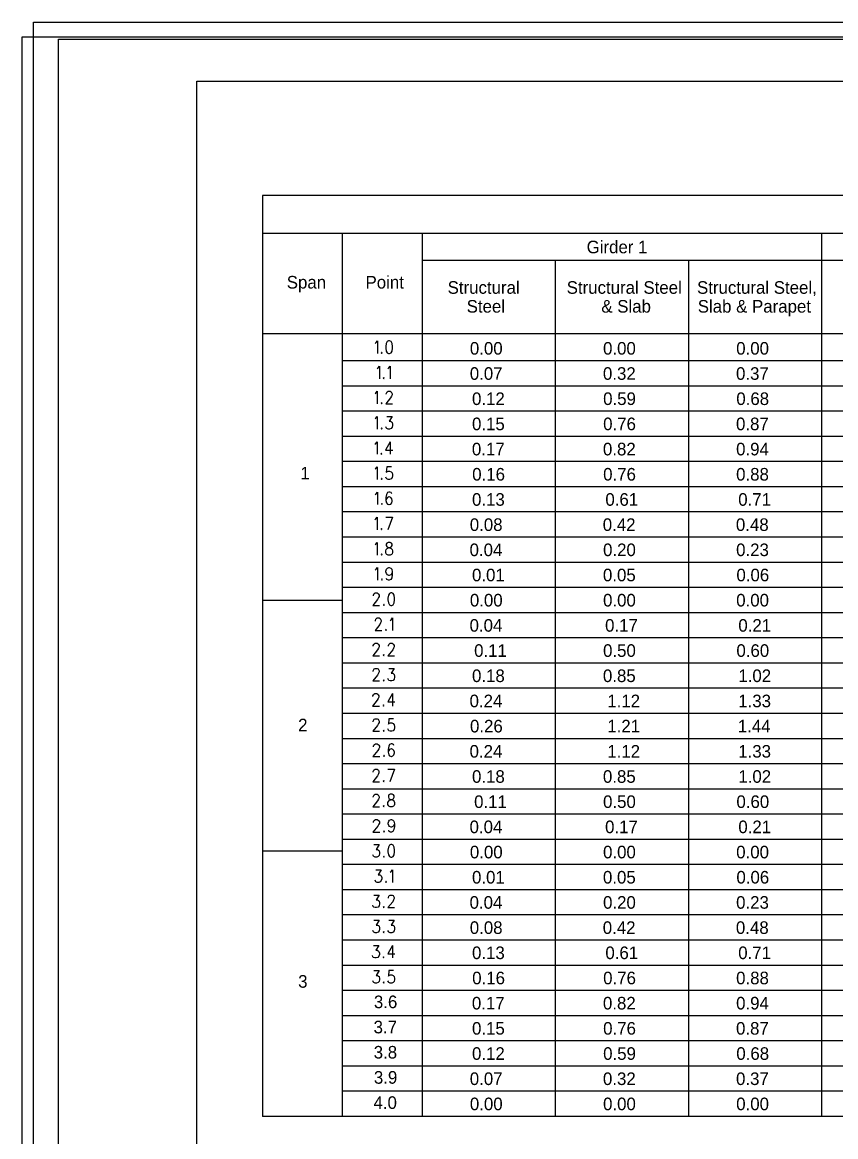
# Model space of a CAD drawing. Extents: x 208.5 to 250.5, y 328.7 to 350.7.
# Drawn here: x 208.55 to 216.62, y 339.65 to 350.71 of the extents above; entities that cross this region are included whole.
import ezdxf

# ---------------------------------------------------------------- set-up
doc = ezdxf.new("R2010")
doc.units = 0
for name, color, linetype in [('border', 7, 'Continuous'), ('Border 2660-Hwy18 - Level 62', 7, 'Continuous'), ('Border 2660-Hwy18 - Level 63', 7, 'Continuous'), ('Level 62 PDF', 7, 'Continuous'), ('Steel', 7, 'Continuous'), ('Text', 7, 'Continuous')]:
    doc.layers.add(name, color=color, linetype=linetype)

msp = doc.modelspace()

# ---------------------------------------------------------------- linework, layer by layer
at = {"layer": 'border'}
for p, q in [((210.28, 350.129), (242.291, 350.129)), ((210.28, 329.584), (210.28, 350.129))]:
    msp.add_line(p, q, dxfattribs=at)
at = {"layer": 'Border 2660-Hwy18 - Level 62'}
msp.add_lwpolyline([(208.659, 350.715), (242.778, 350.715), (242.778, 328.905), (208.659, 328.905)], close=True, dxfattribs=at)
at = {"layer": 'Border 2660-Hwy18 - Level 63'}
msp.add_lwpolyline([(208.548, 350.572), (242.548, 350.572), (242.548, 329.202), (208.548, 329.202)], close=True, dxfattribs=at)
at = {"layer": 'Level 62 PDF'}
msp.add_lwpolyline([(208.909, 350.548), (243.028, 350.548), (243.028, 328.739), (208.909, 328.739)], close=True, dxfattribs=at)
at = {"layer": 'Steel'}
for p, q in [((210.932, 348.995), (210.932, 339.854)), ((232.347, 348.995), (210.932, 348.995)), ((232.347, 348.618), (210.932, 348.618)), ((211.725, 348.618), (211.725, 339.854)), ((212.517, 348.618), (212.517, 339.854)), ((216.483, 348.618), (216.483, 339.854)), ((232.347, 348.349), (212.517, 348.349)), ((213.839, 348.349), (213.839, 339.854)), ((215.161, 348.349), (215.161, 339.854)), ((232.347, 347.623), (210.932, 347.623)), ((232.347, 347.354), (211.725, 347.354)), ((232.347, 347.104), (211.725, 347.104)), ((232.347, 346.854), (211.725, 346.854)), ((232.347, 346.604), (211.725, 346.604)), ((232.347, 346.354), (211.725, 346.354)), ((232.347, 346.104), (211.725, 346.104)), ((232.347, 345.854), (211.725, 345.854)), ((232.347, 345.604), (211.725, 345.604)), ((232.347, 345.354), (211.725, 345.354)), ((232.347, 345.104), (211.725, 345.104)), ((211.725, 344.976), (210.932, 344.976)), ((232.347, 344.854), (211.725, 344.854)), ((232.347, 344.604), (211.725, 344.604)), ((232.347, 344.354), (211.725, 344.354)), ((232.347, 344.104), (211.725, 344.104)), ((232.347, 343.854), (211.725, 343.854)), ((232.347, 343.604), (211.725, 343.604)), ((232.347, 343.354), (211.725, 343.354)), ((232.347, 343.104), (211.725, 343.104)), ((232.347, 342.854), (211.725, 342.854)), ((232.347, 342.604), (211.725, 342.604)), ((211.725, 342.486), (210.932, 342.486)), ((232.347, 342.354), (211.725, 342.354)), ((232.347, 342.104), (211.725, 342.104)), ((232.347, 341.854), (211.725, 341.854)), ((232.347, 341.604), (211.725, 341.604)), ((232.347, 341.354), (211.725, 341.354)), ((232.347, 341.104), (211.725, 341.104)), ((232.347, 340.854), (211.725, 340.854)), ((232.347, 340.604), (211.725, 340.604)), ((232.347, 340.354), (211.725, 340.354)), ((232.347, 340.104), (211.725, 340.104)), ((232.347, 339.854), (210.932, 339.854))]:
    msp.add_line(p, q, dxfattribs=at)
at = {"layer": 'Text'}
for p, q in [((212.202, 346.552), (212.202, 346.427)), ((212.157, 345.802), (212.224, 345.802)), ((212.224, 345.802), (212.176, 345.677)), ((212.223, 344.052), (212.223, 343.927)), ((212.178, 343.302), (212.245, 343.302)), ((212.245, 343.302), (212.197, 343.177)), ((212.223, 341.552), (212.223, 341.427))]:
    msp.add_line(p, q, dxfattribs=at)
for points in [[(212.051, 347.528), (212.06, 347.535), (212.074, 347.552), (212.074, 347.427)], [(212.185, 347.552), (212.171, 347.546), (212.161, 347.528), (212.157, 347.498), (212.157, 347.481), (212.161, 347.451), (212.171, 347.433), (212.185, 347.427), (212.195, 347.427), (212.209, 347.433), (212.219, 347.451), (212.224, 347.481), (212.224, 347.498), (212.219, 347.528), (212.209, 347.546), (212.195, 347.552), (212.185, 347.552)], [(212.116, 347.439), (212.111, 347.433), (212.116, 347.427), (212.121, 347.433), (212.116, 347.439)], [(212.071, 347.278), (212.081, 347.285), (212.095, 347.302), (212.095, 347.177)], [(212.178, 347.278), (212.188, 347.285), (212.202, 347.302), (212.202, 347.177)], [(212.137, 347.189), (212.132, 347.183), (212.137, 347.177), (212.141, 347.183), (212.137, 347.189)], [(212.05, 347.028), (212.059, 347.035), (212.073, 347.052), (212.073, 346.927)], [(212.161, 347.022), (212.161, 347.028), (212.166, 347.04), (212.171, 347.046), (212.18, 347.052), (212.199, 347.052), (212.209, 347.046), (212.213, 347.04), (212.219, 347.028), (212.219, 347.016), (212.213, 347.004), (212.204, 346.986), (212.157, 346.927), (212.224, 346.927)], [(212.115, 346.939), (212.11, 346.933), (212.115, 346.927), (212.12, 346.933), (212.115, 346.939)], [(212.05, 346.778), (212.059, 346.785), (212.073, 346.802), (212.073, 346.677)], [(212.166, 346.802), (212.219, 346.802), (212.19, 346.754), (212.204, 346.754), (212.213, 346.748), (212.219, 346.742), (212.224, 346.725), (212.224, 346.713), (212.219, 346.695), (212.209, 346.683), (212.195, 346.677), (212.18, 346.677), (212.166, 346.683), (212.161, 346.689), (212.157, 346.701)], [(212.115, 346.689), (212.11, 346.683), (212.115, 346.677), (212.12, 346.683), (212.115, 346.689)], [(212.047, 346.528), (212.057, 346.535), (212.071, 346.552), (212.071, 346.427)], [(212.202, 346.552), (212.154, 346.469), (212.226, 346.469)], [(212.113, 346.439), (212.108, 346.433), (212.113, 346.427), (212.117, 346.433), (212.113, 346.439)], [(212.05, 346.278), (212.059, 346.285), (212.073, 346.302), (212.073, 346.177)], [(212.213, 346.302), (212.166, 346.302), (212.161, 346.248), (212.166, 346.254), (212.18, 346.26), (212.195, 346.26), (212.209, 346.254), (212.219, 346.242), (212.224, 346.225), (212.224, 346.213), (212.219, 346.195), (212.209, 346.183), (212.195, 346.177), (212.18, 346.177), (212.166, 346.183), (212.161, 346.189), (212.157, 346.201)], [(212.115, 346.189), (212.11, 346.183), (212.115, 346.177), (212.12, 346.183), (212.115, 346.189)], [(212.052, 346.028), (212.062, 346.035), (212.076, 346.052), (212.076, 345.927)], [(212.217, 346.035), (212.211, 346.046), (212.197, 346.052), (212.187, 346.052), (212.173, 346.046), (212.164, 346.028), (212.159, 345.998), (212.159, 345.969), (212.164, 345.945), (212.173, 345.933), (212.187, 345.927), (212.192, 345.927), (212.206, 345.933), (212.217, 345.945), (212.221, 345.963), (212.221, 345.969), (212.217, 345.986), (212.206, 345.998), (212.192, 346.004), (212.187, 346.004), (212.173, 345.998), (212.164, 345.986), (212.159, 345.969)], [(212.117, 345.939), (212.113, 345.933), (212.117, 345.927), (212.122, 345.933), (212.117, 345.939)], [(212.049, 345.778), (212.058, 345.785), (212.073, 345.802), (212.073, 345.677)], [(212.114, 345.689), (212.11, 345.683), (212.114, 345.677), (212.119, 345.683), (212.114, 345.689)], [(212.05, 345.528), (212.059, 345.535), (212.073, 345.552), (212.073, 345.427)], [(212.18, 345.552), (212.166, 345.546), (212.161, 345.535), (212.161, 345.522), (212.166, 345.51), (212.176, 345.504), (212.195, 345.498), (212.209, 345.492), (212.219, 345.481), (212.224, 345.469), (212.224, 345.451), (212.219, 345.439), (212.213, 345.433), (212.199, 345.427), (212.18, 345.427), (212.166, 345.433), (212.161, 345.439), (212.157, 345.451), (212.157, 345.469), (212.161, 345.481), (212.171, 345.492), (212.185, 345.498), (212.204, 345.504), (212.213, 345.51), (212.219, 345.522), (212.219, 345.535), (212.213, 345.546), (212.199, 345.552), (212.18, 345.552)], [(212.115, 345.439), (212.11, 345.433), (212.115, 345.427), (212.12, 345.433), (212.115, 345.439)], [(212.052, 345.278), (212.062, 345.285), (212.076, 345.302), (212.076, 345.177)], [(212.221, 345.26), (212.216, 345.242), (212.206, 345.231), (212.192, 345.225), (212.187, 345.225), (212.173, 345.231), (212.164, 345.242), (212.159, 345.26), (212.159, 345.266), (212.164, 345.285), (212.173, 345.296), (212.187, 345.302), (212.192, 345.302), (212.206, 345.296), (212.216, 345.285), (212.221, 345.26), (212.221, 345.231), (212.216, 345.201), (212.206, 345.183), (212.192, 345.177), (212.183, 345.177), (212.169, 345.183), (212.164, 345.195)], [(212.117, 345.189), (212.113, 345.183), (212.117, 345.177), (212.122, 345.183), (212.117, 345.189)], [(212.034, 345.022), (212.034, 345.028), (212.038, 345.04), (212.043, 345.046), (212.052, 345.052), (212.071, 345.052), (212.081, 345.046), (212.086, 345.04), (212.091, 345.028), (212.091, 345.016), (212.086, 345.004), (212.076, 344.986), (212.029, 344.927), (212.096, 344.927)], [(212.207, 345.052), (212.193, 345.046), (212.183, 345.028), (212.178, 344.998), (212.178, 344.981), (212.183, 344.951), (212.193, 344.933), (212.207, 344.927), (212.216, 344.927), (212.23, 344.933), (212.241, 344.951), (212.245, 344.981), (212.245, 344.998), (212.241, 345.028), (212.23, 345.046), (212.216, 345.052), (212.207, 345.052)], [(212.138, 344.939), (212.133, 344.933), (212.138, 344.927), (212.142, 344.933), (212.138, 344.939)], [(212.054, 344.772), (212.054, 344.778), (212.059, 344.79), (212.064, 344.796), (212.073, 344.802), (212.092, 344.802), (212.102, 344.796), (212.106, 344.79), (212.112, 344.778), (212.112, 344.766), (212.106, 344.754), (212.097, 344.736), (212.05, 344.677), (212.117, 344.677)], [(212.2, 344.778), (212.21, 344.785), (212.224, 344.802), (212.224, 344.677)], [(212.158, 344.689), (212.154, 344.683), (212.158, 344.677), (212.163, 344.683), (212.158, 344.689)], [(212.033, 344.522), (212.033, 344.528), (212.038, 344.54), (212.042, 344.546), (212.052, 344.552), (212.071, 344.552), (212.08, 344.546), (212.085, 344.54), (212.09, 344.528), (212.09, 344.516), (212.085, 344.504), (212.075, 344.486), (212.028, 344.427), (212.095, 344.427)], [(212.183, 344.522), (212.183, 344.528), (212.188, 344.54), (212.193, 344.546), (212.202, 344.552), (212.221, 344.552), (212.23, 344.546), (212.235, 344.54), (212.241, 344.528), (212.241, 344.516), (212.235, 344.504), (212.226, 344.486), (212.178, 344.427), (212.245, 344.427)], [(212.137, 344.439), (212.132, 344.433), (212.137, 344.427), (212.141, 344.433), (212.137, 344.439)], [(212.033, 344.272), (212.033, 344.278), (212.038, 344.29), (212.042, 344.296), (212.052, 344.302), (212.071, 344.302), (212.08, 344.296), (212.085, 344.29), (212.09, 344.278), (212.09, 344.266), (212.085, 344.254), (212.075, 344.236), (212.028, 344.177), (212.095, 344.177)], [(212.188, 344.302), (212.241, 344.302), (212.211, 344.254), (212.226, 344.254), (212.235, 344.248), (212.241, 344.242), (212.245, 344.225), (212.245, 344.213), (212.241, 344.195), (212.23, 344.183), (212.216, 344.177), (212.202, 344.177), (212.188, 344.183), (212.183, 344.189), (212.178, 344.201)], [(212.137, 344.189), (212.132, 344.183), (212.137, 344.177), (212.141, 344.183), (212.137, 344.189)], [(212.03, 344.022), (212.03, 344.028), (212.035, 344.04), (212.04, 344.046), (212.049, 344.052), (212.068, 344.052), (212.078, 344.046), (212.082, 344.04), (212.088, 344.028), (212.088, 344.016), (212.082, 344.004), (212.073, 343.986), (212.026, 343.927), (212.093, 343.927)], [(212.223, 344.052), (212.176, 343.969), (212.248, 343.969)], [(212.134, 343.939), (212.13, 343.933), (212.134, 343.927), (212.139, 343.933), (212.134, 343.939)], [(212.033, 343.772), (212.033, 343.778), (212.038, 343.79), (212.042, 343.796), (212.052, 343.802), (212.071, 343.802), (212.08, 343.796), (212.085, 343.79), (212.09, 343.778), (212.09, 343.766), (212.085, 343.754), (212.075, 343.736), (212.028, 343.677), (212.095, 343.677)], [(212.235, 343.802), (212.188, 343.802), (212.183, 343.748), (212.188, 343.754), (212.202, 343.76), (212.216, 343.76), (212.23, 343.754), (212.241, 343.742), (212.245, 343.725), (212.245, 343.713), (212.241, 343.695), (212.23, 343.683), (212.216, 343.677), (212.202, 343.677), (212.188, 343.683), (212.183, 343.689), (212.178, 343.701)], [(212.137, 343.689), (212.132, 343.683), (212.137, 343.677), (212.141, 343.683), (212.137, 343.689)], [(212.035, 343.522), (212.035, 343.528), (212.04, 343.54), (212.045, 343.546), (212.054, 343.552), (212.073, 343.552), (212.082, 343.546), (212.087, 343.54), (212.093, 343.528), (212.093, 343.516), (212.087, 343.504), (212.078, 343.486), (212.03, 343.427), (212.097, 343.427)], [(212.238, 343.535), (212.233, 343.546), (212.219, 343.552), (212.209, 343.552), (212.195, 343.546), (212.186, 343.528), (212.181, 343.498), (212.181, 343.469), (212.186, 343.445), (212.195, 343.433), (212.209, 343.427), (212.214, 343.427), (212.228, 343.433), (212.238, 343.445), (212.243, 343.463), (212.243, 343.469), (212.238, 343.486), (212.228, 343.498), (212.214, 343.504), (212.209, 343.504), (212.195, 343.498), (212.186, 343.486), (212.181, 343.469)], [(212.139, 343.439), (212.134, 343.433), (212.139, 343.427), (212.144, 343.433), (212.139, 343.439)], [(212.032, 343.272), (212.032, 343.278), (212.037, 343.29), (212.041, 343.296), (212.051, 343.302), (212.07, 343.302), (212.079, 343.296), (212.084, 343.29), (212.089, 343.278), (212.089, 343.266), (212.084, 343.254), (212.075, 343.236), (212.027, 343.177), (212.094, 343.177)], [(212.136, 343.189), (212.131, 343.183), (212.136, 343.177), (212.141, 343.183), (212.136, 343.189)], [(212.033, 343.022), (212.033, 343.028), (212.038, 343.04), (212.042, 343.046), (212.052, 343.052), (212.071, 343.052), (212.08, 343.046), (212.085, 343.04), (212.09, 343.028), (212.09, 343.016), (212.085, 343.004), (212.075, 342.986), (212.028, 342.927), (212.095, 342.927)], [(212.202, 343.052), (212.188, 343.046), (212.183, 343.035), (212.183, 343.022), (212.188, 343.01), (212.197, 343.004), (212.216, 342.998), (212.23, 342.992), (212.241, 342.981), (212.245, 342.969), (212.245, 342.951), (212.241, 342.939), (212.235, 342.933), (212.221, 342.927), (212.202, 342.927), (212.188, 342.933), (212.183, 342.939), (212.178, 342.951), (212.178, 342.969), (212.183, 342.981), (212.193, 342.992), (212.207, 342.998), (212.226, 343.004), (212.235, 343.01), (212.241, 343.022), (212.241, 343.035), (212.235, 343.046), (212.221, 343.052), (212.202, 343.052)], [(212.137, 342.939), (212.132, 342.933), (212.137, 342.927), (212.141, 342.933), (212.137, 342.939)], [(212.035, 342.772), (212.035, 342.778), (212.04, 342.79), (212.045, 342.796), (212.054, 342.802), (212.073, 342.802), (212.082, 342.796), (212.087, 342.79), (212.093, 342.778), (212.093, 342.766), (212.087, 342.754), (212.078, 342.736), (212.03, 342.677), (212.097, 342.677)], [(212.243, 342.76), (212.237, 342.742), (212.228, 342.731), (212.214, 342.725), (212.209, 342.725), (212.195, 342.731), (212.186, 342.742), (212.181, 342.76), (212.181, 342.766), (212.186, 342.785), (212.195, 342.796), (212.209, 342.802), (212.214, 342.802), (212.228, 342.796), (212.237, 342.785), (212.243, 342.76), (212.243, 342.731), (212.237, 342.701), (212.228, 342.683), (212.214, 342.677), (212.204, 342.677), (212.19, 342.683), (212.186, 342.695)], [(212.139, 342.689), (212.134, 342.683), (212.139, 342.677), (212.144, 342.683), (212.139, 342.689)], [(212.038, 342.552), (212.091, 342.552), (212.062, 342.504), (212.076, 342.504), (212.086, 342.498), (212.091, 342.492), (212.096, 342.475), (212.096, 342.463), (212.091, 342.445), (212.081, 342.433), (212.067, 342.427), (212.052, 342.427), (212.038, 342.433), (212.034, 342.439), (212.029, 342.451)], [(212.207, 342.552), (212.193, 342.546), (212.183, 342.528), (212.178, 342.498), (212.178, 342.481), (212.183, 342.451), (212.193, 342.433), (212.207, 342.427), (212.216, 342.427), (212.23, 342.433), (212.241, 342.451), (212.245, 342.481), (212.245, 342.498), (212.241, 342.528), (212.23, 342.546), (212.216, 342.552), (212.207, 342.552)], [(212.138, 342.439), (212.133, 342.433), (212.138, 342.427), (212.142, 342.433), (212.138, 342.439)], [(212.059, 342.302), (212.112, 342.302), (212.083, 342.254), (212.097, 342.254), (212.106, 342.248), (212.112, 342.242), (212.117, 342.225), (212.117, 342.213), (212.112, 342.195), (212.102, 342.183), (212.088, 342.177), (212.073, 342.177), (212.059, 342.183), (212.054, 342.189), (212.05, 342.201)], [(212.2, 342.278), (212.21, 342.285), (212.224, 342.302), (212.224, 342.177)], [(212.158, 342.189), (212.154, 342.183), (212.158, 342.177), (212.163, 342.183), (212.158, 342.189)], [(212.038, 342.052), (212.09, 342.052), (212.061, 342.004), (212.075, 342.004), (212.085, 341.998), (212.09, 341.992), (212.095, 341.975), (212.095, 341.963), (212.09, 341.945), (212.08, 341.933), (212.066, 341.927), (212.052, 341.927), (212.038, 341.933), (212.033, 341.939), (212.028, 341.951)], [(212.183, 342.022), (212.183, 342.028), (212.188, 342.04), (212.193, 342.046), (212.202, 342.052), (212.221, 342.052), (212.23, 342.046), (212.235, 342.04), (212.241, 342.028), (212.241, 342.016), (212.235, 342.004), (212.226, 341.986), (212.178, 341.927), (212.245, 341.927)], [(212.137, 341.939), (212.132, 341.933), (212.137, 341.927), (212.141, 341.933), (212.137, 341.939)], [(212.038, 341.802), (212.09, 341.802), (212.061, 341.754), (212.075, 341.754), (212.085, 341.748), (212.09, 341.742), (212.095, 341.725), (212.095, 341.713), (212.09, 341.695), (212.08, 341.683), (212.066, 341.677), (212.052, 341.677), (212.038, 341.683), (212.033, 341.689), (212.028, 341.701)], [(212.188, 341.802), (212.241, 341.802), (212.211, 341.754), (212.226, 341.754), (212.235, 341.748), (212.241, 341.742), (212.245, 341.725), (212.245, 341.713), (212.241, 341.695), (212.23, 341.683), (212.216, 341.677), (212.202, 341.677), (212.188, 341.683), (212.183, 341.689), (212.178, 341.701)], [(212.137, 341.689), (212.132, 341.683), (212.137, 341.677), (212.141, 341.683), (212.137, 341.689)], [(212.035, 341.552), (212.088, 341.552), (212.059, 341.504), (212.073, 341.504), (212.082, 341.498), (212.088, 341.492), (212.093, 341.475), (212.093, 341.463), (212.088, 341.445), (212.078, 341.433), (212.063, 341.427), (212.049, 341.427), (212.035, 341.433), (212.03, 341.439), (212.026, 341.451)], [(212.223, 341.552), (212.176, 341.469), (212.248, 341.469)], [(212.134, 341.439), (212.13, 341.433), (212.134, 341.427), (212.139, 341.433), (212.134, 341.439)], [(212.038, 341.302), (212.09, 341.302), (212.061, 341.254), (212.075, 341.254), (212.085, 341.248), (212.09, 341.242), (212.095, 341.225), (212.095, 341.213), (212.09, 341.195), (212.08, 341.183), (212.066, 341.177), (212.052, 341.177), (212.038, 341.183), (212.033, 341.189), (212.028, 341.201)], [(212.235, 341.302), (212.188, 341.302), (212.183, 341.248), (212.188, 341.254), (212.202, 341.26), (212.216, 341.26), (212.23, 341.254), (212.241, 341.242), (212.245, 341.225), (212.245, 341.213), (212.241, 341.195), (212.23, 341.183), (212.216, 341.177), (212.202, 341.177), (212.188, 341.183), (212.183, 341.189), (212.178, 341.201)], [(212.137, 341.189), (212.132, 341.183), (212.137, 341.177), (212.141, 341.183), (212.137, 341.189)]]:
    msp.add_lwpolyline(points, dxfattribs=at)

# ---------------------------------------------------------------- texts
for s, p in [('Girder 1', (214.151, 348.422)), ('Span', (211.174, 348.072)), ('Point', (211.956, 348.072)), ('Structural', (212.771, 348.02)), ('Structural Steel', (213.953, 348.02)), ('Structural Steel,', (215.247, 348.02)), ('Steel', (212.96, 347.833)), ('& Slab', (214.297, 347.833)), ('Slab & Parapet', (215.254, 347.833)), ('0.00', (212.992, 347.416)), ('0.00', (214.314, 347.416)), ('0.00', (215.636, 347.416)), ('0.07', (212.991, 347.166)), ('0.32', (214.313, 347.166)), ('0.37', (215.634, 347.166)), ('0.12', (213.013, 346.916)), ('0.59', (214.315, 346.916)), ('0.68', (215.637, 346.916)), ('0.15', (213.013, 346.666)), ('0.76', (214.315, 346.666)), ('0.87', (215.634, 346.666)), ('0.17', (213.012, 346.416)), ('0.82', (214.313, 346.416)), ('0.94', (215.635, 346.416)), ('1', (211.309, 346.177)), ('0.16', (213.015, 346.166)), ('0.76', (214.315, 346.166)), ('0.88', (215.635, 346.166)), ('0.13', (213.013, 345.916)), ('0.61', (214.337, 345.916)), ('0.71', (215.656, 345.916)), ('0.08', (212.991, 345.666)), ('0.42', (214.311, 345.666)), ('0.48', (215.633, 345.666)), ('0.04', (212.989, 345.416)), ('0.20', (214.314, 345.416)), ('0.23', (215.635, 345.416)), ('0.01', (213.013, 345.166)), ('0.05', (214.313, 345.166)), ('0.06', (215.638, 345.166)), ('0.00', (212.992, 344.916)), ('0.00', (214.314, 344.916)), ('0.00', (215.636, 344.916)), ('0.04', (212.989, 344.666)), ('0.17', (214.334, 344.666)), ('0.21', (215.657, 344.666)), ('0.11', (213.034, 344.416)), ('0.50', (214.314, 344.416)), ('0.60', (215.638, 344.416)), ('0.18', (213.013, 344.166)), ('0.85', (214.313, 344.166)), ('1.02', (215.657, 344.166)), ('0.24', (212.989, 343.916)), ('1.12', (214.356, 343.916)), ('1.33', (215.656, 343.916)), ('2', (211.287, 343.677)), ('0.26', (212.993, 343.666)), ('1.21', (214.356, 343.666)), ('1.44', (215.652, 343.666)), ('0.24', (212.989, 343.416)), ('1.12', (214.356, 343.416)), ('1.33', (215.656, 343.416)), ('0.18', (213.013, 343.166)), ('0.85', (214.313, 343.166)), ('1.02', (215.657, 343.166)), ('0.11', (213.034, 342.916)), ('0.50', (214.314, 342.916)), ('0.60', (215.638, 342.916)), ('0.04', (212.989, 342.666)), ('0.17', (214.334, 342.666)), ('0.21', (215.657, 342.666)), ('0.00', (212.992, 342.416)), ('0.00', (214.314, 342.416)), ('0.00', (215.636, 342.416)), ('0.01', (213.013, 342.166)), ('0.05', (214.313, 342.166)), ('0.06', (215.638, 342.166)), ('0.04', (212.989, 341.916)), ('0.20', (214.314, 341.916)), ('0.23', (215.635, 341.916)), ('0.08', (212.991, 341.666)), ('0.42', (214.311, 341.666)), ('0.48', (215.633, 341.666)), ('0.13', (213.013, 341.416)), ('0.61', (214.337, 341.416)), ('0.71', (215.656, 341.416)), ('0.16', (213.015, 341.166)), ('0.76', (214.315, 341.166)), ('0.88', (215.635, 341.166)), ('3', (211.287, 341.132)), ('3.6', (212.039, 340.929)), ('0.17', (213.012, 340.916)), ('0.82', (214.313, 340.916)), ('0.94', (215.635, 340.916)), ('3.7', (212.036, 340.679)), ('0.15', (213.013, 340.666)), ('0.76', (214.315, 340.666)), ('0.87', (215.634, 340.666)), ('3.8', (212.037, 340.429)), ('0.12', (213.013, 340.416)), ('0.59', (214.315, 340.416)), ('0.68', (215.637, 340.416)), ('3.9', (212.039, 340.179)), ('0.07', (212.991, 340.166)), ('0.32', (214.313, 340.166)), ('0.37', (215.634, 340.166)), ('4.0', (212.035, 339.929)), ('0.00', (212.992, 339.916)), ('0.00', (214.314, 339.916)), ('0.00', (215.636, 339.916))]:
    msp.add_text(s, height=0.125, dxfattribs=at).set_placement(p)

doc.saveas('drawing.dxf')
